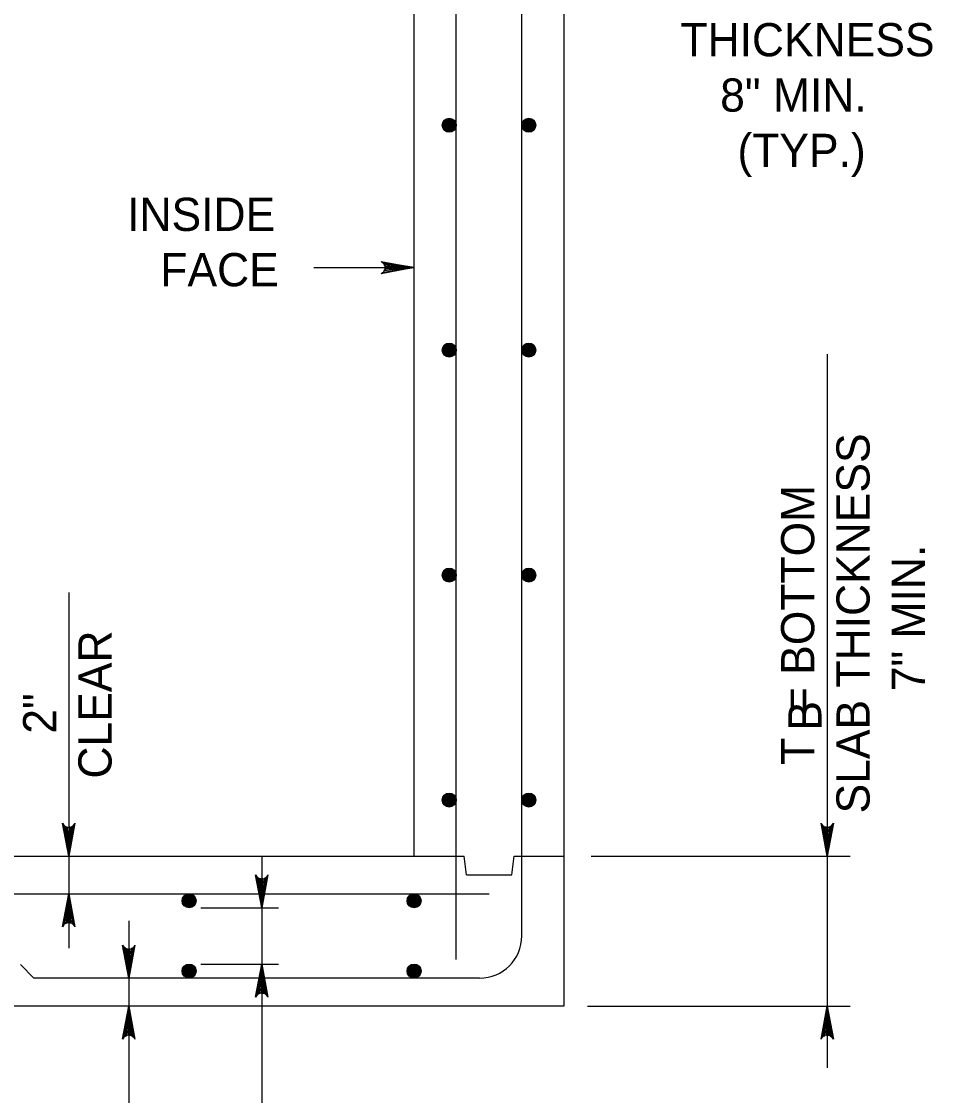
# Model space of a CAD drawing. Extents: x -6420 to 49575, y -4552 to 11624.
# Drawn here: x 3399.6 to 3669.7, y 2263.2 to 2581.5 of the extents above; entities that cross this region are included whole.
import ezdxf

# ---------------------------------------------------------------- set-up
doc = ezdxf.new("R2010")
doc.units = 0
doc.layers.add('1', color=7, linetype='Continuous')

msp = doc.modelspace()

# ---------------------------------------------------------------- linework, layer by layer
at = {"layer": '1'}
for p, q in [((3560.44, 2822.95), (3560.44, 2289.62)), ((3547.94, 2310.45), (3547.94, 2814.62)), ((3516, 2334.07), (3516, 2806.29)), ((3528.5, 2303.51), (3528.5, 2797.95)), ((3486.31, 2508.51), (3516, 2508.51)), ((3638.46, 2482.88), (3638.46, 2271.33)), ((3413.63, 2412.2), (3413.63, 2306.82)), ((3115.99, 2334.07), (3516, 2334.07)), ((3470.88, 2334.11), (3470.88, 2231.29)), ((3516, 2334.07), (3530.81, 2334.07)), ((3531.51, 2328.52), (3530.81, 2334.07)), ((3544.94, 2328.52), (3545.63, 2334.07)), ((3545.63, 2334.07), (3560.44, 2334.07)), ((3568.5, 2334.07), (3645.22, 2334.07)), ((3531.51, 2328.52), (3544.94, 2328.52)), ((3093.77, 2322.95), (3538.22, 2322.95)), ((3452.84, 2318.79), (3475.82, 2318.79)), ((3431.45, 2314.91), (3431.45, 2212.61)), ((3399.33, 2301.95), (3403.33, 2297.95)), ((3452.84, 2302.11), (3475.82, 2302.11)), ((3535.44, 2297.95), (3403.33, 2297.95)), ((3560.44, 2289.62), (3071.54, 2289.62)), ((3567.38, 2289.62), (3645.22, 2289.62))]:
    msp.add_line(p, q, dxfattribs=at)
for points in [[(3516, 2508.51), (3506.21, 2506.68), (3506.59, 2506.94), (3506.97, 2507.2), (3507.16, 2507.53), (3507.35, 2507.85), (3507.41, 2508.18), (3507.47, 2508.51), (3507.41, 2508.84), (3507.35, 2509.17), (3507.16, 2509.49), (3506.97, 2509.82), (3506.59, 2510.08), (3506.21, 2510.35), (3516, 2508.51), (3506.59, 2510.08), (3506.97, 2509.82), (3516, 2508.51), (3507.16, 2509.49), (3507.35, 2509.17), (3516, 2508.51), (3507.41, 2508.84), (3507.47, 2508.51), (3516, 2508.51), (3507.41, 2508.18), (3507.35, 2507.85), (3516, 2508.51), (3507.16, 2507.53), (3506.97, 2507.2), (3516, 2508.51), (3506.59, 2506.94)], [(3413.63, 2334.07), (3411.8, 2343.85), (3412.06, 2343.48), (3412.32, 2343.1), (3412.65, 2342.9), (3412.98, 2342.71), (3413.31, 2342.65), (3413.63, 2342.6), (3413.96, 2342.65), (3414.29, 2342.71), (3414.62, 2342.9), (3414.95, 2343.1), (3415.21, 2343.48), (3415.47, 2343.85), (3413.63, 2334.07), (3415.21, 2343.48), (3414.95, 2343.1), (3413.63, 2334.07), (3414.62, 2342.9), (3414.29, 2342.71), (3413.63, 2334.07), (3413.96, 2342.65), (3413.63, 2342.6), (3413.63, 2334.07), (3413.31, 2342.65), (3412.98, 2342.71), (3413.63, 2334.07), (3412.65, 2342.9), (3412.32, 2343.1), (3413.63, 2334.07), (3412.06, 2343.48)], [(3638.46, 2334.07), (3636.62, 2343.85), (3636.88, 2343.48), (3637.14, 2343.1), (3637.47, 2342.9), (3637.8, 2342.71), (3638.13, 2342.65), (3638.46, 2342.6), (3638.78, 2342.65), (3639.11, 2342.71), (3639.44, 2342.9), (3639.77, 2343.1), (3640.03, 2343.48), (3640.29, 2343.85), (3638.46, 2334.07), (3640.03, 2343.48), (3639.77, 2343.1), (3638.46, 2334.07), (3639.44, 2342.9), (3639.11, 2342.71), (3638.46, 2334.07), (3638.78, 2342.65), (3638.46, 2342.6), (3638.46, 2334.07), (3638.13, 2342.65), (3637.8, 2342.71), (3638.46, 2334.07), (3637.47, 2342.9), (3637.14, 2343.1), (3638.46, 2334.07), (3636.88, 2343.48)], [(3470.88, 2318.79), (3469.04, 2328.57), (3469.31, 2328.2), (3469.57, 2327.82), (3469.89, 2327.62), (3470.22, 2327.43), (3470.55, 2327.37), (3470.88, 2327.32), (3471.21, 2327.37), (3471.54, 2327.43), (3471.86, 2327.62), (3472.19, 2327.82), (3472.45, 2328.2), (3472.71, 2328.57), (3470.88, 2318.79), (3472.45, 2328.2), (3472.19, 2327.82), (3470.88, 2318.79), (3471.86, 2327.62), (3471.54, 2327.43), (3470.88, 2318.79), (3471.21, 2327.37), (3470.88, 2327.32), (3470.88, 2318.79), (3470.55, 2327.37), (3470.22, 2327.43), (3470.88, 2318.79), (3469.89, 2327.62), (3469.57, 2327.82), (3470.88, 2318.79), (3469.31, 2328.2)], [(3413.63, 2322.95), (3415.47, 2313.17), (3415.21, 2313.55), (3414.95, 2313.92), (3414.62, 2314.12), (3414.29, 2314.31), (3413.96, 2314.37), (3413.63, 2314.42), (3413.31, 2314.37), (3412.98, 2314.31), (3412.65, 2314.12), (3412.32, 2313.92), (3412.06, 2313.55), (3411.8, 2313.17), (3413.63, 2322.95), (3412.06, 2313.55), (3412.32, 2313.92), (3413.63, 2322.95), (3412.65, 2314.12), (3412.98, 2314.31), (3413.63, 2322.95), (3413.31, 2314.37), (3413.63, 2314.42), (3413.63, 2322.95), (3413.96, 2314.37), (3414.29, 2314.31), (3413.63, 2322.95), (3414.62, 2314.12), (3414.95, 2313.92), (3413.63, 2322.95), (3415.21, 2313.55)], [(3431.45, 2297.95), (3429.61, 2307.74), (3429.88, 2307.36), (3430.14, 2306.98), (3430.47, 2306.79), (3430.79, 2306.6), (3431.12, 2306.54), (3431.45, 2306.48), (3431.78, 2306.54), (3432.11, 2306.6), (3432.43, 2306.79), (3432.76, 2306.98), (3433.02, 2307.36), (3433.28, 2307.74), (3431.45, 2297.95), (3433.02, 2307.36), (3432.76, 2306.98), (3431.45, 2297.95), (3432.43, 2306.79), (3432.11, 2306.6), (3431.45, 2297.95), (3431.78, 2306.54), (3431.45, 2306.48), (3431.45, 2297.95), (3431.12, 2306.54), (3430.79, 2306.6), (3431.45, 2297.95), (3430.47, 2306.79), (3430.14, 2306.98), (3431.45, 2297.95), (3429.88, 2307.36)], [(3470.88, 2302.11), (3472.71, 2292.33), (3472.45, 2292.7), (3472.19, 2293.08), (3471.86, 2293.28), (3471.54, 2293.47), (3471.21, 2293.53), (3470.88, 2293.58), (3470.55, 2293.53), (3470.22, 2293.47), (3469.89, 2293.28), (3469.57, 2293.08), (3469.31, 2292.7), (3469.04, 2292.33), (3470.88, 2302.11), (3469.31, 2292.7), (3469.57, 2293.08), (3470.88, 2302.11), (3469.89, 2293.28), (3470.22, 2293.47), (3470.88, 2302.11), (3470.55, 2293.53), (3470.88, 2293.58), (3470.88, 2302.11), (3471.21, 2293.53), (3471.54, 2293.47), (3470.88, 2302.11), (3471.86, 2293.28), (3472.19, 2293.08), (3470.88, 2302.11), (3472.45, 2292.7)], [(3431.45, 2289.62), (3433.28, 2279.83), (3433.02, 2280.21), (3432.76, 2280.59), (3432.43, 2280.78), (3432.11, 2280.98), (3431.78, 2281.03), (3431.45, 2281.09), (3431.12, 2281.03), (3430.79, 2280.98), (3430.47, 2280.78), (3430.14, 2280.59), (3429.88, 2280.21), (3429.61, 2279.83), (3431.45, 2289.62), (3429.88, 2280.21), (3430.14, 2280.59), (3431.45, 2289.62), (3430.47, 2280.78), (3430.79, 2280.98), (3431.45, 2289.62), (3431.12, 2281.03), (3431.45, 2281.09), (3431.45, 2289.62), (3431.78, 2281.03), (3432.11, 2280.98), (3431.45, 2289.62), (3432.43, 2280.78), (3432.76, 2280.59), (3431.45, 2289.62), (3433.02, 2280.21)], [(3638.46, 2289.62), (3640.29, 2279.83), (3640.03, 2280.21), (3639.77, 2280.59), (3639.44, 2280.78), (3639.11, 2280.98), (3638.78, 2281.03), (3638.46, 2281.09), (3638.13, 2281.03), (3637.8, 2280.98), (3637.47, 2280.78), (3637.14, 2280.59), (3636.88, 2280.21), (3636.62, 2279.83), (3638.46, 2289.62), (3636.88, 2280.21), (3637.14, 2280.59), (3638.46, 2289.62), (3637.47, 2280.78), (3637.8, 2280.98), (3638.46, 2289.62), (3638.13, 2281.03), (3638.46, 2281.09), (3638.46, 2289.62), (3638.78, 2281.03), (3639.11, 2280.98), (3638.46, 2289.62), (3639.44, 2280.78), (3639.77, 2280.59), (3638.46, 2289.62), (3640.03, 2280.21)]]:
    msp.add_lwpolyline(points, dxfattribs=at)
for centre, radius in [((3526.42, 2550.73), 2.08), ((3526.42, 2550.73), 1.94), ((3526.42, 2550.73), 1.79), ((3526.42, 2550.73), 1.64), ((3526.42, 2550.73), 1.49), ((3526.42, 2550.73), 1.34), ((3526.42, 2550.73), 1.2), ((3526.42, 2550.73), 1.05), ((3526.42, 2550.73), 0.9), ((3526.42, 2550.73), 0.752), ((3526.42, 2550.73), 0.604), ((3526.42, 2550.73), 0.456), ((3526.42, 2550.73), 0.308), ((3526.42, 2550.73), 0.16), ((3550.02, 2550.73), 2.08), ((3550.02, 2550.73), 1.94), ((3550.02, 2550.73), 1.79), ((3550.02, 2550.73), 1.64), ((3550.02, 2550.73), 1.49), ((3550.02, 2550.73), 1.34), ((3550.02, 2550.73), 1.2), ((3550.02, 2550.73), 1.05), ((3550.02, 2550.73), 0.9), ((3550.02, 2550.73), 0.752), ((3550.02, 2550.73), 0.604), ((3550.02, 2550.73), 0.456), ((3550.02, 2550.73), 0.308), ((3550.02, 2550.73), 0.16), ((3526.42, 2484.07), 2.08), ((3550.02, 2484.07), 2.08), ((3526.42, 2484.07), 1.94), ((3526.42, 2484.07), 1.79), ((3526.42, 2484.07), 1.64), ((3526.42, 2484.07), 1.49), ((3526.42, 2484.07), 1.34), ((3526.42, 2484.07), 1.2), ((3526.42, 2484.07), 1.05), ((3526.42, 2484.07), 0.9), ((3526.42, 2484.07), 0.752), ((3526.42, 2484.07), 0.604), ((3526.42, 2484.07), 0.456), ((3526.42, 2484.07), 0.308), ((3526.42, 2484.07), 0.16), ((3550.02, 2484.07), 1.94), ((3550.02, 2484.07), 1.79), ((3550.02, 2484.07), 1.64), ((3550.02, 2484.07), 1.49), ((3550.02, 2484.07), 1.34), ((3550.02, 2484.07), 1.2), ((3550.02, 2484.07), 1.05), ((3550.02, 2484.07), 0.9), ((3550.02, 2484.07), 0.752), ((3550.02, 2484.07), 0.604), ((3550.02, 2484.07), 0.456), ((3550.02, 2484.07), 0.308), ((3550.02, 2484.07), 0.16), ((3526.42, 2417.4), 2.08), ((3526.42, 2417.4), 1.94), ((3550.02, 2417.4), 2.08), ((3550.02, 2417.4), 1.94), ((3526.42, 2417.4), 1.79), ((3526.42, 2417.4), 1.64), ((3526.42, 2417.4), 1.49), ((3526.42, 2417.4), 1.34), ((3526.42, 2417.4), 1.2), ((3526.42, 2417.4), 1.05), ((3526.42, 2417.4), 0.9), ((3526.42, 2417.4), 0.752), ((3526.42, 2417.4), 0.604), ((3526.42, 2417.4), 0.456), ((3526.42, 2417.4), 0.308), ((3526.42, 2417.4), 0.16), ((3550.02, 2417.4), 1.79), ((3550.02, 2417.4), 1.64), ((3550.02, 2417.4), 1.49), ((3550.02, 2417.4), 1.34), ((3550.02, 2417.4), 1.2), ((3550.02, 2417.4), 1.05), ((3550.02, 2417.4), 0.9), ((3550.02, 2417.4), 0.752), ((3550.02, 2417.4), 0.604), ((3550.02, 2417.4), 0.456), ((3550.02, 2417.4), 0.308), ((3550.02, 2417.4), 0.16), ((3526.42, 2350.73), 2.08), ((3526.42, 2350.73), 1.94), ((3526.42, 2350.73), 1.79), ((3550.02, 2350.73), 2.08), ((3550.02, 2350.73), 1.94), ((3550.02, 2350.73), 1.79), ((3526.42, 2350.73), 1.64), ((3526.42, 2350.73), 1.49), ((3526.42, 2350.73), 1.34), ((3526.42, 2350.73), 1.2), ((3526.42, 2350.73), 1.05), ((3526.42, 2350.73), 0.9), ((3526.42, 2350.73), 0.752), ((3526.42, 2350.73), 0.604), ((3526.42, 2350.73), 0.456), ((3526.42, 2350.73), 0.308), ((3526.42, 2350.73), 0.16), ((3550.02, 2350.73), 1.64), ((3550.02, 2350.73), 1.49), ((3550.02, 2350.73), 1.34), ((3550.02, 2350.73), 1.2), ((3550.02, 2350.73), 1.05), ((3550.02, 2350.73), 0.9), ((3550.02, 2350.73), 0.752), ((3550.02, 2350.73), 0.604), ((3550.02, 2350.73), 0.456), ((3550.02, 2350.73), 0.308), ((3550.02, 2350.73), 0.16), ((3449.32, 2320.87), 2.08), ((3449.32, 2320.87), 1.94), ((3449.32, 2320.87), 1.79), ((3449.32, 2320.87), 1.64), ((3449.32, 2320.87), 1.49), ((3449.32, 2320.87), 1.34), ((3449.32, 2320.87), 1.2), ((3449.32, 2320.87), 1.05), ((3449.32, 2320.87), 0.9), ((3449.32, 2320.87), 0.752), ((3449.32, 2320.87), 0.604), ((3449.32, 2320.87), 0.456), ((3449.32, 2320.87), 0.308), ((3449.32, 2320.87), 0.16), ((3516, 2320.87), 2.08), ((3516, 2320.87), 1.94), ((3516, 2320.87), 1.79), ((3516, 2320.87), 1.64), ((3516, 2320.87), 1.49), ((3516, 2320.87), 1.34), ((3516, 2320.87), 1.2), ((3516, 2320.87), 1.05), ((3516, 2320.87), 0.9), ((3516, 2320.87), 0.752), ((3516, 2320.87), 0.604), ((3516, 2320.87), 0.456), ((3516, 2320.87), 0.308), ((3516, 2320.87), 0.16), ((3449.32, 2300.04), 2.08), ((3449.32, 2300.04), 1.94), ((3449.32, 2300.04), 1.79), ((3449.32, 2300.04), 1.64), ((3449.32, 2300.04), 1.49), ((3516, 2300.04), 2.08), ((3516, 2300.04), 1.94), ((3516, 2300.04), 1.79), ((3516, 2300.04), 1.64), ((3516, 2300.04), 1.49), ((3449.32, 2300.04), 1.34), ((3449.32, 2300.04), 1.2), ((3449.32, 2300.04), 1.05), ((3449.32, 2300.04), 0.9), ((3449.32, 2300.04), 0.752), ((3449.32, 2300.04), 0.604), ((3449.32, 2300.04), 0.456), ((3449.32, 2300.04), 0.308), ((3449.32, 2300.04), 0.16), ((3516, 2300.04), 1.34), ((3516, 2300.04), 1.2), ((3516, 2300.04), 1.05), ((3516, 2300.04), 0.9), ((3516, 2300.04), 0.752), ((3516, 2300.04), 0.604), ((3516, 2300.04), 0.456), ((3516, 2300.04), 0.308), ((3516, 2300.04), 0.16)]:
    msp.add_circle(centre, radius, dxfattribs=at)
msp.add_arc((3535.44, 2310.45), 12.5, 270, 0, dxfattribs=at)

# ---------------------------------------------------------------- texts
for s, p in [('THICKNESS', (3594.95, 2571.15)), ('8" MIN.', (3606.73, 2554.75)), ('(TYP.)', (3611.85, 2538.35)), ('INSIDE', (3430.96, 2519.4)), ('FACE', (3440.8, 2503))]:
    msp.add_text(s, height=9.843, dxfattribs=at).set_placement(p)
for s, height, p in [('SLAB THICKNESS', 9.8425, (3651.03, 2346.76)), ('T  = BOTTOM', 9.8425, (3634.63, 2361.14)), ('7" MIN.', 9.843, (3667.44, 2382.96)), ('CLEAR', 9.843, (3426.35, 2357.09)), ('2"', 9.843, (3409.95, 2370.38)), ('B', 9.84, (3636.78, 2371.3))]:
    msp.add_text(s, height=height, rotation=90, dxfattribs=at).set_placement(p)

doc.saveas('drawing.dxf')
